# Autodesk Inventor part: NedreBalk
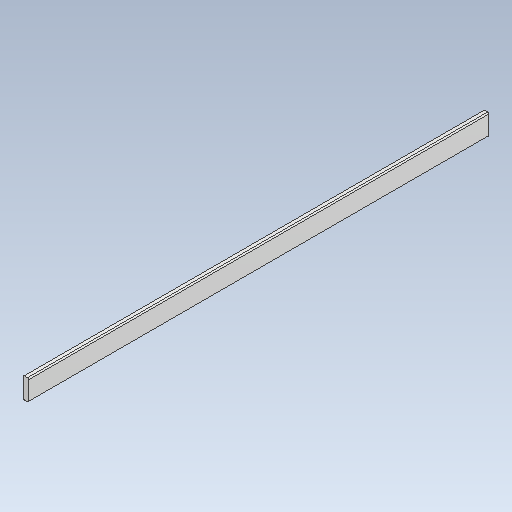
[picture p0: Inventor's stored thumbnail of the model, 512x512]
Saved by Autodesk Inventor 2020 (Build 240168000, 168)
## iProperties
Created: 2019-06
Part Number: NedreBalk
Material: Aluminum
Document SubType Name: Modeling
Designer: cl
Density: 2.7 g/cm^3
Appearance: Satin
Author: cl
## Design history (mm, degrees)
sketch "Sketch1"
  geometry: L1 (0, 0)-(7, 0); L2 (12, -5)-(12, -85); L3 (7, -90)-(0, -90); L4 (0, 0)-(0, -90); L5 (0, 0)-(-7, 0); L6 (-12, -5)-(-12, -85); L7 (-7, -90)-(0, -90); A1 r 5 centre (7, -5) between (12, -5) and (7, 0); A2 r 5 centre (7, -85) between (7, -90) and (12, -85); A3 r 5 centre (-7, -5) between (-7, 0) and (-12, -5); A4 r 5 centre (-7, -85) between (-12, -85) and (-7, -90); 4 further points
  constraints: 14 end point, 8 point on circle, 8 point on line, 8 symmetric about line, 4 centre point, 4 tangent, 2 perpendicular, 1 equal radius, 1 horizontal, 1 vertical, 2 other
  dimensions: "d0" = 12 distance of L1.start point (12, 0); "d1" = 90 distance of point (12, 0) point (12, -90); "d2" = 5 radius of A1
extrude "Extrusion1" new body sketch "Sketch1" distance "d3" = 1970 (computed from Dagbredd); taper "d4" = 0 deg
body "Solid1"
